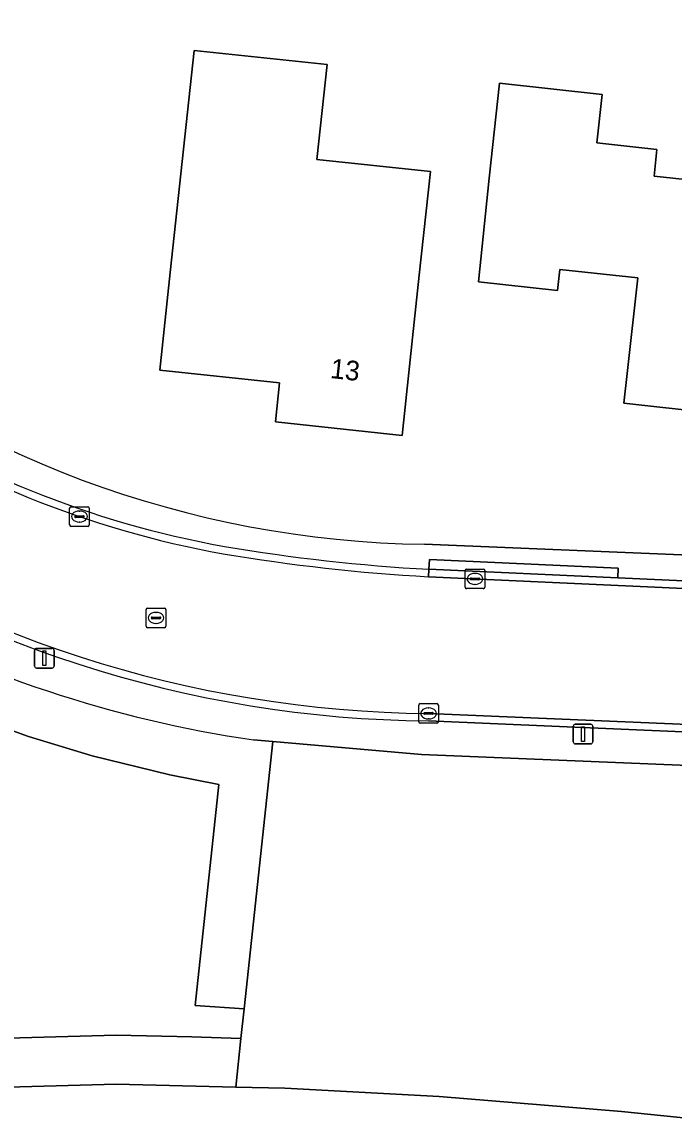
# Model space of a CAD drawing. Extents: x 162156 to 163172, y 378995 to 380779.
# Drawn here: x 162318 to 162351.2, y 380387.4 to 380442.9 of the extents above; entities that cross this region are included whole.
import ezdxf

# ---------------------------------------------------------------- set-up
doc = ezdxf.new("R2010")
doc.units = 0
for name, color, linetype in [('IMGEO_Erf', 7, 'Continuous'), ('IMGEO_Groenvoorziening', 7, 'Continuous'), ('IMGEO_Kolk', 7, 'Continuous'), ('IMGEO_Lichtmast', 7, 'Continuous'), ('IMGEO_Pand', 7, 'Continuous'), ('IMGEO_Pand_nummerreeks', 7, 'Continuous'), ('IMGEO_Rijbaan_lokaal_gesloten', 7, 'Continuous'), ('IMGEO_Rijbaan_lokaal_open', 7, 'Continuous'), ('IMGEO_Rioolput', 7, 'Continuous'), ('IMGEO_Voetpad_halfverhard', 7, 'Continuous'), ('IMGEO_Voetpad_open', 7, 'Continuous')]:
    doc.layers.add(name, color=color, linetype=linetype)

msp = doc.modelspace()

# ---------------------------------------------------------------- linework, layer by layer
at = {"layer": 'IMGEO_Erf'}
for points in [[(162338.487, 380416.274), (162374.063, 380414.801), (162374.064, 380415.292), (162391.176, 380414.602), (162391.48, 380417.235), (162395.391, 380416.901), (162395.142, 380414.475), (162395.612, 380414.46), (162395.861, 380416.623), (162399.632, 380416.174), (162399.509, 380414.336), (162417.691, 380413.608), (162418.08, 380417.313), (162421.672, 380416.83), (162425.078, 380416.626), (162424.841, 380413.184), (162445.895, 380412.275), (162450.873, 380411.981), (162450.992, 380415.077), (162450.558, 380415.103), (162452.698, 380468.838)], [(162357.384, 380422.494), (162348.641, 380423.458), (162348.807, 380424.963), (162349.344, 380429.836), (162345.371, 380430.274), (162345.253, 380429.204), (162341.232, 380429.647), (162341.782, 380434.926), (162342.314, 380439.755), (162347.528, 380439.181), (162347.257, 380436.722), (162350.326, 380436.384), (162350.176, 380435.024), (162353.822, 380434.622)]]:
    msp.add_lwpolyline(points, dxfattribs=at)
msp.add_lwpolyline([(162338.791, 380435.256), (162338.225, 380429.979), (162337.883, 380426.788), (162337.35, 380421.816), (162330.894, 380422.508), (162331.107, 380424.491), (162325.008, 380425.145), (162325.541, 380430.117), (162326.754, 380441.429), (162333.529, 380440.703), (162333.012, 380435.876)], close=True, dxfattribs=at)
msp.add_arc((162339.23, 380468.3), 52.031, 229.9413, 269.1819, dxfattribs=at)
at = {"layer": 'IMGEO_Groenvoorziening'}
for points in [[(162292.663, 380426.336), (162290.851, 380424.607), (162293.243, 380422.067), (162297.087, 380418.509), (162300.374, 380415.888), (162304.305, 380413.175), (162307.47, 380411.288), (162309.521, 380410.201), (162312.248, 380408.879), (162315.649, 380407.458), (162318.322, 380406.488), (162321.569, 380405.495), (162325.521, 380404.532), (162328.013, 380404.042), (162326.806, 380392.789), (162329.302, 380392.613), (162330.761, 380406.226)], [(162294.561, 380390.49), (162322.784, 380391.276), (162326.634, 380391.182), (162329.14, 380391.098), (162329.302, 380392.613), (162326.806, 380392.789), (162328.013, 380404.042), (162325.521, 380404.532), (162321.569, 380405.495), (162318.322, 380406.488), (162315.649, 380407.458)], [(162330.761, 380406.226), (162329.788, 380406.31)]]:
    msp.add_lwpolyline(points, dxfattribs=at)
for points in [[(162392.234, 380403.338), (162338.342, 380405.57), (162330.761, 380406.226), (162329.302, 380392.613), (162329.14, 380391.098), (162328.875, 380388.627), (162331.384, 380388.566), (162339.242, 380388.156), (162348.52, 380387.387), (162357.976, 380386.415), (162364.918, 380385.435), (162371.193, 380384.55), (162378.044, 380383.27)], [(162329.14, 380391.098), (162326.634, 380391.182), (162322.784, 380391.276), (162294.561, 380390.49), (162294.605, 380387.99), (162322.79, 380388.775), (162328.875, 380388.627)]]:
    msp.add_lwpolyline(points, close=True, dxfattribs=at)
msp.add_arc((162338.754, 380467.357), 61.702, 221.66891, 261.64439, dxfattribs=at)
at = {"layer": 'IMGEO_Kolk'}
for p, q in [((162320.42, 380417.261), (162320.42, 380418.113)), ((162320.495, 380418.187), (162321.347, 380418.187)), ((162321.421, 380418.113), (162321.421, 380417.261)), ((162320.679, 380417.681), (162320.679, 380417.693)), ((162321.117, 380417.644), (162320.719, 380417.644)), ((162320.722, 380417.73), (162321.12, 380417.73)), ((162320.908, 380417.967), (162320.933, 380417.967)), ((162321.163, 380417.693), (162321.163, 380417.681)), ((162321.347, 380417.187), (162320.495, 380417.187)), ((162320.931, 380417.407), (162320.906, 380417.407)), ((162340.556, 380414.087), (162340.556, 380414.939)), ((162340.631, 380415.013), (162341.483, 380415.013)), ((162341.044, 380414.793), (162341.069, 380414.793)), ((162341.557, 380414.939), (162341.557, 380414.087)), ((162340.815, 380414.507), (162340.815, 380414.519)), ((162341.253, 380414.47), (162340.855, 380414.47)), ((162340.858, 380414.556), (162341.256, 380414.556)), ((162341.067, 380414.233), (162341.042, 380414.233)), ((162341.299, 380414.519), (162341.299, 380414.507)), ((162341.483, 380414.013), (162340.631, 380414.013)), ((162338.268, 380408.158), (162339.12, 380408.158)), ((162338.193, 380407.232), (162338.193, 380408.084)), ((162338.452, 380407.652), (162338.452, 380407.664)), ((162338.89, 380407.615), (162338.492, 380407.615)), ((162338.495, 380407.701), (162338.893, 380407.701)), ((162338.681, 380407.938), (162338.706, 380407.938)), ((162338.936, 380407.664), (162338.936, 380407.652)), ((162339.194, 380408.084), (162339.194, 380407.232)), ((162339.12, 380407.158), (162338.268, 380407.158)), ((162338.704, 380407.378), (162338.679, 380407.378))]:
    msp.add_line(p, q, dxfattribs=at)
for points in [[(162320.42, 380417.261), (162320.42, 380418.113)], [(162320.495, 380418.187), (162321.347, 380418.187)], [(162321.421, 380418.113), (162321.421, 380417.261)], [(162321.347, 380417.187), (162320.495, 380417.187)], [(162340.556, 380414.087), (162340.556, 380414.939)], [(162340.631, 380415.013), (162341.483, 380415.013)], [(162341.557, 380414.939), (162341.557, 380414.087)], [(162341.483, 380414.013), (162340.631, 380414.013)], [(162338.268, 380408.158), (162339.12, 380408.158)], [(162338.193, 380407.232), (162338.193, 380408.084)], [(162339.194, 380408.084), (162339.194, 380407.232)], [(162339.12, 380407.158), (162338.268, 380407.158)]]:
    msp.add_lwpolyline(points, dxfattribs=at)
for centre, radius, start, end in [((162320.497, 380418.111), 0.0765, 91.552, 178.448), ((162320.497, 380418.111), 0.0765, 91.552, 178.448), ((162321.345, 380418.111), 0.0765, 1.552, 88.448), ((162321.345, 380418.111), 0.0765, 1.552, 88.448), ((162320.719, 380417.69), 0.0403, 85.8775, 175.7526), ((162320.716, 380417.68), 0.0366, 178.938, 274.7102), ((162321.12, 380417.687), 0.043, 264.8664, 352.4533), ((162321.124, 380417.692), 0.0386, 1.7309, 96.639), ((162320.497, 380417.263), 0.0765, 181.552, 268.448), ((162320.497, 380417.263), 0.0765, 181.552, 268.448), ((162321.345, 380417.263), 0.0765, 271.552, 358.448), ((162321.345, 380417.263), 0.0765, 271.552, 358.448), ((162340.633, 380414.937), 0.0765, 91.552, 178.448), ((162340.633, 380414.937), 0.0765, 91.552, 178.448), ((162341.481, 380414.937), 0.0765, 1.552, 88.448), ((162341.481, 380414.937), 0.0765, 1.552, 88.448), ((162340.855, 380414.516), 0.0403, 85.8775, 175.7526), ((162340.852, 380414.506), 0.0366, 178.938, 274.7102), ((162341.256, 380414.513), 0.043, 264.8664, 352.4533), ((162341.26, 380414.518), 0.0386, 1.7309, 96.639), ((162340.633, 380414.089), 0.0765, 181.552, 268.448), ((162340.633, 380414.089), 0.0765, 181.552, 268.448), ((162341.481, 380414.089), 0.0765, 271.552, 358.448), ((162341.481, 380414.089), 0.0765, 271.552, 358.448), ((162338.27, 380408.082), 0.0765, 91.552, 178.448), ((162338.27, 380408.082), 0.0765, 91.552, 178.448), ((162339.118, 380408.082), 0.0765, 1.552, 88.448), ((162339.118, 380408.082), 0.0765, 1.552, 88.448), ((162338.492, 380407.661), 0.0403, 85.8775, 175.7526), ((162338.489, 380407.651), 0.0366, 178.938, 274.7102), ((162338.893, 380407.658), 0.043, 264.8664, 352.4533), ((162338.897, 380407.663), 0.0386, 1.7309, 96.639), ((162338.27, 380407.234), 0.0765, 181.552, 268.448), ((162338.27, 380407.234), 0.0765, 181.552, 268.448), ((162339.118, 380407.234), 0.0765, 271.552, 358.448), ((162339.118, 380407.234), 0.0765, 271.552, 358.448)]:
    msp.add_arc(centre, radius, start, end, dxfattribs=at)
for centre, major_axis, ratio, start_param, end_param in [((162320.907, 380417.687), (-0.387, 0.002), 0.722429, 4.712389, 7.853982), ((162320.932, 380417.687), (-0.39, 0.002), 0.717154, 1.570796, 4.712389), ((162341.043, 380414.513), (-0.387, 0.002), 0.722429, 4.712389, 7.853982), ((162341.068, 380414.513), (-0.39, 0.002), 0.717154, 1.570796, 4.712389), ((162338.68, 380407.658), (-0.387, 0.002), 0.722429, 4.712389, 7.853982), ((162338.705, 380407.658), (-0.39, 0.002), 0.717154, 1.570796, 4.712389)]:
    msp.add_ellipse(centre, major_axis=major_axis, ratio=ratio, start_param=start_param, end_param=end_param, dxfattribs=at)
at = {"layer": 'IMGEO_Lichtmast'}
for p, q in [((162318.734, 380410.972), (162319.524, 380410.972)), ((162319.524, 380410.972), (162318.734, 380410.972)), ((162318.634, 380410.072), (162318.634, 380410.872)), ((162318.634, 380410.872), (162318.634, 380410.072)), ((162319.624, 380410.872), (162319.624, 380410.072)), ((162319.624, 380410.072), (162319.624, 380410.872)), ((162319.524, 380409.972), (162318.734, 380409.972)), ((162318.734, 380409.972), (162319.524, 380409.972)), ((162346.161, 380407.109), (162346.951, 380407.109)), ((162346.951, 380407.109), (162346.161, 380407.109)), ((162346.061, 380406.209), (162346.061, 380407.009)), ((162346.061, 380407.009), (162346.061, 380406.209)), ((162347.051, 380407.009), (162347.051, 380406.209)), ((162347.051, 380406.209), (162347.051, 380407.009)), ((162346.951, 380406.109), (162346.161, 380406.109)), ((162346.161, 380406.109), (162346.951, 380406.109))]:
    msp.add_line(p, q, dxfattribs=at)
for points in [[(162319.054, 380410.847), (162319.204, 380410.847), (162319.204, 380410.097), (162319.054, 380410.097), (162319.054, 380410.847)], [(162346.481, 380406.984), (162346.631, 380406.984), (162346.631, 380406.234), (162346.481, 380406.234), (162346.481, 380406.984)]]:
    msp.add_lwpolyline(points, dxfattribs=at)
for centre, start, end in [((162318.734, 380410.872), 90, 180), ((162318.734, 380410.872), 90, 180), ((162319.524, 380410.872), 0, 90), ((162319.524, 380410.872), 360, 90), ((162318.734, 380410.072), 180, 270), ((162318.734, 380410.072), 180, 270), ((162319.524, 380410.072), 270, 0), ((162319.524, 380410.072), 270, 0), ((162346.161, 380407.009), 90, 180), ((162346.161, 380407.009), 90, 180), ((162346.951, 380407.009), 0, 90), ((162346.951, 380407.009), 360, 90), ((162346.161, 380406.209), 180, 270), ((162346.161, 380406.209), 180, 270), ((162346.951, 380406.209), 270, 0), ((162346.951, 380406.209), 270, 0)]:
    msp.add_arc(centre, 0.1, start, end, dxfattribs=at)
at = {"layer": 'IMGEO_Pand'}
for points in [[(162338.791, 380435.256), (162333.012, 380435.876), (162333.529, 380440.703), (162326.754, 380441.429), (162325.541, 380430.117), (162325.008, 380425.145), (162331.107, 380424.491), (162330.894, 380422.508), (162337.35, 380421.816), (162337.883, 380426.788), (162338.225, 380429.979)], [(162358.591, 380434.097), (162358.832, 380436.413), (162354.06, 380436.909), (162353.822, 380434.622), (162350.176, 380435.024), (162350.326, 380436.384), (162347.257, 380436.722), (162347.528, 380439.181), (162342.314, 380439.755), (162341.782, 380434.926), (162341.232, 380429.647), (162345.253, 380429.204), (162345.371, 380430.274), (162349.344, 380429.836), (162348.807, 380424.963), (162348.641, 380423.458), (162357.384, 380422.494)]]:
    msp.add_lwpolyline(points, close=True, dxfattribs=at)
at = {"layer": 'IMGEO_Rijbaan_lokaal_gesloten'}
for points in [[(162338.699, 380414.62), (162338.716, 380415)], [(162338.698, 380407.659), (162358.725, 380406.8), (162401.879, 380404.979), (162422.859, 380404.132), (162442.493, 380403.083), (162449.884, 380402.368), (162459.408, 380401.551), (162478.597, 380398.952), (162500, 380396.023), (162509.495, 380394.723), (162521.145, 380393.198), (162522.1, 380400.031), (162500, 380403.006), (162458.711, 380408.563), (162457.772, 380408.665), (162450.751, 380409.341), (162448.628, 380409.546), (162401.068, 380411.851), (162359.121, 380413.685), (162338.699, 380414.62)]]:
    msp.add_lwpolyline(points, dxfattribs=at)
msp.add_lwpolyline([(162450.786, 380409.707), (162449.329, 380409.791), (162445.612, 380410.005), (162442.244, 380410.187), (162424.699, 380411.133), (162417.472, 380411.523), (162399.373, 380412.304), (162395.383, 380412.476), (162394.939, 380412.495), (162390.952, 380412.667), (162373.968, 380413.4), (162373.168, 380413.436), (162365.002, 380413.802), (162359.138, 380414.065), (162348.33, 380414.56), (162338.716, 380415), (162338.699, 380414.62), (162359.121, 380413.685), (162401.068, 380411.851), (162448.628, 380409.546), (162450.751, 380409.341)], close=True, dxfattribs=at)
for centre, radius, start, end in [((162336.984, 380464.689), 49.672, 212.3125, 259.855), ((162336.984, 380464.689), 49.672, 212.3125, 259.855), ((162336.966, 380464.663), 49.263, 212.3026, 259.8669), ((162339.223, 380466.918), 59.261, 234.58401, 269.49205), ((162343.708, 380506.559), 91.695, 260.32573, 266.8792), ((162343.788, 380507.276), 92.795, 260.35149, 266.85636), ((162343.788, 380507.276), 92.795, 260.35149, 266.85636)]:
    msp.add_arc(centre, radius, start, end, dxfattribs=at)
at = {"layer": 'IMGEO_Rijbaan_lokaal_open'}
for points in [[(162401.879, 380404.979), (162358.725, 380406.8), (162338.698, 380407.659)], [(162338.688, 380407.279), (162358.709, 380406.42), (162401.863, 380404.599), (162422.841, 380403.752), (162442.465, 380402.704), (162449.849, 380401.99), (162459.366, 380401.173), (162478.546, 380398.575), (162500, 380395.64), (162509.445, 380394.346), (162521.087, 380392.822), (162521.145, 380393.198), (162509.495, 380394.723), (162500, 380396.023), (162478.597, 380398.952), (162459.408, 380401.551), (162449.884, 380402.368), (162442.493, 380403.083), (162422.859, 380404.132), (162401.879, 380404.979)]]:
    msp.add_lwpolyline(points, dxfattribs=at)
for centre, radius, start, end in [((162339.213, 380466.886), 59.61, 234.57985, 269.49554), ((162339.223, 380466.918), 59.261, 234.58401, 269.49205)]:
    msp.add_arc(centre, radius, start, end, dxfattribs=at)
at = {"layer": 'IMGEO_Rioolput'}
for p, q in [((162324.317, 380412.1), (162324.317, 380412.952)), ((162324.392, 380413.026), (162325.244, 380413.026)), ((162324.619, 380412.569), (162325.017, 380412.569)), ((162324.805, 380412.806), (162324.83, 380412.806)), ((162325.318, 380412.952), (162325.318, 380412.1)), ((162325.244, 380412.026), (162324.392, 380412.026)), ((162324.576, 380412.52), (162324.576, 380412.532)), ((162325.014, 380412.483), (162324.616, 380412.483)), ((162324.828, 380412.246), (162324.803, 380412.246)), ((162325.06, 380412.532), (162325.06, 380412.52))]:
    msp.add_line(p, q, dxfattribs=at)
for points in [[(162324.317, 380412.1), (162324.317, 380412.952)], [(162324.392, 380413.026), (162325.244, 380413.026)], [(162325.318, 380412.952), (162325.318, 380412.1)], [(162325.244, 380412.026), (162324.392, 380412.026)]]:
    msp.add_lwpolyline(points, dxfattribs=at)
for centre, radius, start, end in [((162324.394, 380412.95), 0.0765, 91.552, 178.448), ((162324.394, 380412.95), 0.0765, 91.552, 178.448), ((162324.616, 380412.529), 0.0403, 85.8775, 175.7526), ((162325.021, 380412.531), 0.0386, 1.7309, 96.639), ((162325.242, 380412.95), 0.0765, 1.552, 88.448), ((162325.242, 380412.95), 0.0765, 1.552, 88.448), ((162324.394, 380412.102), 0.0765, 181.552, 268.448), ((162324.394, 380412.102), 0.0765, 181.552, 268.448), ((162324.613, 380412.519), 0.0366, 178.938, 274.7102), ((162325.017, 380412.526), 0.043, 264.8664, 352.4533), ((162325.242, 380412.102), 0.0765, 271.552, 358.448), ((162325.242, 380412.102), 0.0765, 271.552, 358.448)]:
    msp.add_arc(centre, radius, start, end, dxfattribs=at)
for centre, major_axis, ratio, start_param, end_param in [((162324.804, 380412.526), (-0.387, 0.002), 0.722429, 4.712389, 7.853982), ((162324.829, 380412.526), (-0.39, 0.002), 0.717154, 1.570796, 4.712389)]:
    msp.add_ellipse(centre, major_axis=major_axis, ratio=ratio, start_param=start_param, end_param=end_param, dxfattribs=at)
at = {"layer": 'IMGEO_Voetpad_halfverhard'}
msp.add_lwpolyline([(162378.044, 380383.27), (162371.193, 380384.55), (162364.918, 380385.435), (162357.976, 380386.415), (162348.52, 380387.387), (162339.242, 380388.156), (162331.384, 380388.566), (162328.875, 380388.627), (162322.79, 380388.775), (162294.605, 380387.99), (162286.823, 380387.773), (162282.71, 380387.858), (162272.847, 380388.577), (162256.83, 380390.364)], dxfattribs=at)
at = {"layer": 'IMGEO_Voetpad_open'}
for points in [[(162338.716, 380415), (162338.741, 380415.499), (162348.355, 380415.059), (162348.33, 380414.56), (162359.138, 380414.065), (162365.002, 380413.802), (162365.026, 380414.301), (162373.192, 380413.935), (162373.168, 380413.436), (162373.968, 380413.4), (162374.063, 380414.801), (162338.487, 380416.274)], [(162459.366, 380401.173), (162449.849, 380401.99), (162442.465, 380402.704), (162422.841, 380403.752), (162401.863, 380404.599), (162358.709, 380406.42), (162338.688, 380407.279)], [(162329.788, 380406.31), (162330.761, 380406.226), (162338.342, 380405.57), (162392.234, 380403.338), (162422.555, 380402.082), (162437.447, 380401.191), (162459.542, 380399.35), (162483.054, 380396.268), (162486.399, 380395.83), (162491.443, 380395.165), (162497.556, 380394.347), (162500, 380394.02), (162500.64, 380393.934), (162579.396, 380383.398), (162579.648, 380385.1), (162544.102, 380389.81), (162521.087, 380392.822), (162509.445, 380394.346), (162500, 380395.64), (162478.546, 380398.575), (162459.366, 380401.173)]]:
    msp.add_lwpolyline(points, dxfattribs=at)
msp.add_lwpolyline([(162348.33, 380414.56), (162348.355, 380415.059), (162338.741, 380415.499), (162338.716, 380415)], close=True, dxfattribs=at)
for centre, radius, start, end in [((162336.966, 380464.663), 49.263, 212.3026, 259.8669), ((162339.23, 380468.3), 52.031, 229.9413, 269.1819), ((162338.754, 380467.357), 61.702, 221.66891, 261.64439), ((162339.213, 380466.886), 59.61, 234.57985, 269.49554), ((162343.708, 380506.559), 91.695, 260.32573, 266.8792)]:
    msp.add_arc(centre, radius, start, end, dxfattribs=at)

# ---------------------------------------------------------------- texts
at = {"layer": 'IMGEO_Pand_nummerreeks'}
msp.add_text('13', height=1, rotation=353.882, dxfattribs=at).set_placement((162333.66, 380424.745))

doc.saveas('drawing.dxf')
